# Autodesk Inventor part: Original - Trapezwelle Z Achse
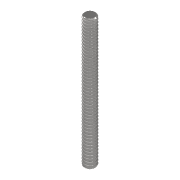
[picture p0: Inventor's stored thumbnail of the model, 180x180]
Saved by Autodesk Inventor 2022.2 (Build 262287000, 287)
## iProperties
Created: 2024-09
Part Number: Original - Trapezwelle Z Achse
Material: Acciaio inossidabile
Document SubType Name: Modeling
Designer: 18907419
Density: 8 g/cm^3
Appearance: Semilucidato
Author: 18907419
Revision Number: ANY
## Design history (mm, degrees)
feature "Schnitt-Rotation1"
node "Solido1"
